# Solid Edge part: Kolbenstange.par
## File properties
Username: bmolnar
Dokumentum tartalom típus: 0
Author: bmolnar
Last saved by: bmolnar
Revision: 80
Sűrűség: 0,000 kg/m^3
Pontosság: 0,990
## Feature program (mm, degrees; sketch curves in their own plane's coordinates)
base feature "unnamed BaseFeature 1"
sketch for "Furat_1" plane through (-15, 0, 0) normal (-1, 0, 0) x-axis (0, 1, 0)
  hole centre (0, 0) bore radius 2.4585
hole "Furat_1" nominal diameter 6 finite  ThreadDepth = 15 mm; StartChamferOffset = 0.7 mm; StartChamferAngle = 45 deg; VBottomAngle = 118 deg
sketch for "Kihúzás_1" plane through (23.5, 0, 0) normal (1, 0, 0) x-axis (0, -1, 0)
  circle centre (0, 0) radius 12.5
extrude "Kihúzás_1" add finite 14 along +normal
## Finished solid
Body 1: solid body, 14 faces, 20 edges, 8 vertices.
  Faces by surface: plane 7, cylinder 4, cone 2, torus 1
  Edges by curve: circle 10, line 6, ellipse 2, intersection 2
Bounding box of the edges (mm; curved faces can reach further): 52.500 x 25.000 x 25.000, from (-15, -12.5, -12.5) to (37.5, 12.5, 12.5).
Cylindrical faces by radius (mm): R2.4585 x2, R5 x1, R12.5 x1
Conical faces (half-angle, radius in mm at the cone's reference point): 45 deg R3.1585 x1, 59 deg R2.4585 x1
Toroidal faces (ring radius, tube radius in mm): R3.8 r1.2 x1
Planar faces by outward normal: +x 1, +z 1, -x 2, -z 1, oblique 2
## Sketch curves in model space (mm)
circle centre (23.5, 0, 0) radius 12.5
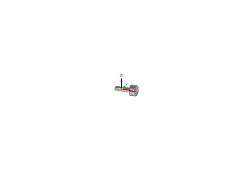
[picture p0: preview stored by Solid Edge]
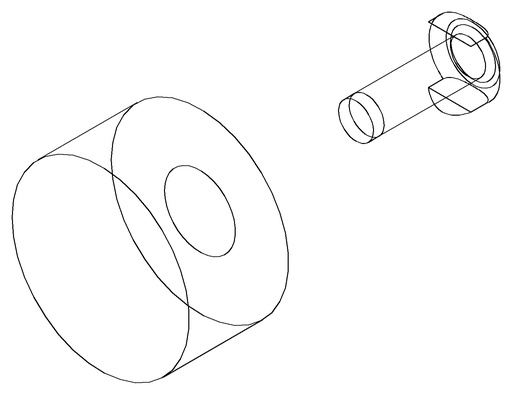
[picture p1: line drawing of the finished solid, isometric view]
